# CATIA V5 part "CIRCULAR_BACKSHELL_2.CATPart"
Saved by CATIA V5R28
Part number: CIRCULAR_BACKSHELL_2
Revision: --A
Publications: "Logical Termination.1", "BCP", "BCPRPoint_generated(BCP)", "BCPPlane_generated(BCP)", "BaCP", "Face_generated(BaCP)", "Face_generated(BaCP).1", "MasterKeywayAxis", "Axis_generated(BaCP)"
Bounding box of the stored display mesh (mm): x 0 to 66.178, y -14.383 to 14.383, z -15.367 to 15.317
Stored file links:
  C:\Users\ajc8720\Documents\BOEING_WORK\0001-2CES\004-AP242\Boeing-Generic_Harness_R3\CIRCULAR_BACKSHELL_2.CATPart
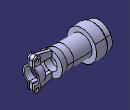
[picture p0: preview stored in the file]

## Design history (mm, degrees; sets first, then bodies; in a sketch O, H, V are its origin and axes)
Parameters
  PartNumber = "CIRCULAR_BACKSHELL_2"
AxisSystem1 "MasterKeywayAxis": origin (0, 0, 0), X (1, 0, 0), Y (0, 1, 0), Z (0, 0, 1)
Set1
  Point1: (34.417 {= Sketch2.distance(P3 V)}, 12.7, 0)
  Plane1: type 1Line1Pt, RefPoint Point1, Line Sketch2.L1
  Point2: type OnCurve, Support Sketch2.L4, Ratio 0.5
  Line1: type PtDir, RefPoint Point2, Direction (0, 1, 0), Start 0, End 5.08
  Point3: type OnCurve, Support Line1, Ratio 0.5
  Plane2: type 1Line1Pt, RefPoint Point3, Line Sketch2.L4
  Point4: type Center, Curve edge [face of Shaft1 from Sketch1.L5 | face of Shaft1 from Sketch1.L6]
  Plane3: type Tangent, Support face of Shaft1 from Sketch1.L5, RefPoint Point4
  Plane4: type OffsetPt, RefPlane Plane2, RefPoint Sketch2.P10
  Line2: type PtPt, FirstPoint vertex [face of Pad3 from Sketch5.L6 | face of Pad3 from Sketch5.L12 | end face of Pad3], SecondPoint vertex [face of Pad3 from Sketch5.L3 | face of Pad3 from Sketch5.L4 | start face of Pad3]
  Point5: type OnCurve, Support Line2, Ratio 0.5
  Plane5: type Tangent, Support face of Pad3 from Sketch5.L6, RefPoint Point5
Set2 "EGF"
  Set3 "BCP"
    Point6 "BCPRPoint": type Center, Curve edge [start face of Pad4 | face of Pad4 from Sketch6.A3]
    Plane6 "BCPPlane": type Tangent, Support start face of Pad4, RefPoint Point6
  Set4 "BaCP"
    Point7 "BaCPRPoint": type Center, Curve edge [face of Shaft1 from Sketch1.L6 | face of Shaft1 from Sketch1.L7]
    Plane7 "BaCPCPlane": type Tangent, Support face of Shaft1 from Sketch1.L7, RefPoint Point7
    Line3 "BaCPCLine": type PtDir, RefPoint Point7, Direction (0, 1, 0), Start 0, End 5.08
Body1 (main body)
  Sketch1 on xy-plane, origin (0, 0, 0), H (1, 0, 0), V (0, 1, 0)
    line L1 (0, 10.3124) -> (0, 12.7889)
    line L2 (0, 12.7889) -> (4.7625, 12.7889)
    point P3 (4.7625, 12.7889)
    line L3 (4.7625, 12.7889) -> (6.3754, 14.4018)
    line L4 (6.3754, 14.4018) -> (16.764, 14.4018)
    line L5 (16.764, 14.4018) -> (16.764, 6.477)
    line L6 (16.764, 6.477) -> (7.747, 6.477)
    line L7 (7.747, 6.477) -> (7.747, 10.3124)
    line L8 (7.747, 10.3124) -> (0, 10.3124)
    axis line L9 (-2.2417, 0) -> (20.7737, 0)
    point P9 (-2.2417, 0)
    distance P3 L1 = 4.7625
    angle L3 L4 = 45
    distance L1 L7 = 7.747
    distance L1 L5 = 16.764
    distance L6 H = 6.477
    distance L8 H = 10.3124
    distance L2 H = 12.7889
    distance L4 H = 14.4018
    vertical: L1 V, L5 V, L7 V
    horizontal: L2 H, L4 H, L6 H, L8 H, L9 H
    coincidence: L1 V, P9 H
  Shaft1: profile Sketch1, axis Sketch1.L9, angle 360
  Sketch2 on zx-plane, origin (0, 0, 0), H (-1, 0, 0), V (0, 0, 1)
    line L1 (-34.417, 0) -> (-34.4237, 15.3041)
    line L2 (-34.417, 0) -> (-36.5055, 0)
    point P3 (-34.417, 0)
    line L3 (-34.417, 0) -> (-40.767, -0.0055)
    line L4 (-40.767, -0.0055) -> (-40.6855, -93.3721)
    reference projected point E1 (-34.417, 0) from Point1
    point P7 (-40.767, -0.0055)
    line L5 (-47.117, -0.0111) -> (-47.0355, -93.3776)
    construction line L6 (-40.767, -0.0055) -> (-47.117, -0.0111)
    construction line L7 (-40.6855, -93.3721) -> (-47.0355, -93.3776)
    point P10 (-47.117, -0.0111)
    point P11 (-34.417, 0)
    angle L1 V = 0.025
    distance P3 V = 34.417
    distance L4 E1 = 6.35
    angle L3 H = 0.05
    distance L4 L5 = 6.35
    horizontal: L2 H
    coincidence: L2 P3, L1 P3, L2 H, L4 P7, L3 P7, L3 P10, L5 P10, L1 P11, L3 P11
    perpendicularity: L4 L3, L6 L4, L6 L5, L7 L4, L7 L5
  Sketch3 on Plane3, origin (16.764, 0, 0), H (0, -1, 0), V (0, 0, 1)
    circle A1 centre (0, 0) radius 6.477
    circle A2 centre (0, 0) radius 9.906
    radius A1 = 6.477
    radius A2 = 9.906
  Pad1: profile Sketch3, direction (1, 0, 0), up to Plane1
  Sketch4 on Plane2, origin (40.6592, 0, -123.5794), H (0, 1, 0), V (0.0009, 0, 1)
    circle A1 centre (0, 123.5739) radius 6.477
    point P1 (0, 123.5739)
    circle A2 centre (0, 123.5739) radius 9.906
    reference projected point E1 (0, 123.5739) from Sketch2.P7
    radius A1 = 6.477
    radius A2 = 9.906
    coincidence: P1 V, P1 E1
  Pad2: profile Sketch4, direction (-1, 0, 0.0009), up to Plane1
  Sketch5 on zx-plane, origin (0, 0, 0), H (-1, 0, 0), V (0, 0, 1)
    point P1 (0, 0)
    construction line L1 (0, 0) -> (-34.417, 0)
    point P2 (-34.417, 0)
    construction line L2 (-34.417, 0) -> (-47.117, -0.0111)
    point P3 (-47.117, -0.0111)
    point P4 (-47.0636, -61.233)
    line L3 (-66.1776, 12.1389) -> (-66.1725, 6.3223)
    point P5 (-66.1725, 6.3223)
    line L4 (-66.1725, 6.3223) -> (-59.8225, 6.3278)
    line L5 (-47.1226, 6.4659) -> (-47.127, 11.4756)
    circle A1 centre (-63.0026, 12.1417) radius 1.8256
    arc A2 centre (-63.0026, 12.1417) radius 3.175 from (-66.1776, 12.1389) to (-62.2384, 15.2233) cw
    point P7 (-66.1776, 12.1389)
    point P8 (-62.2383, 15.2233)
    point P10 (-66.1614, -6.3777)
    point P12 (-66.1564, -12.1943)
    line L6 (-66.1564, -12.1943) -> (-66.1614, -6.3777)
    circle A3 centre (-62.9814, -12.1915) radius 1.8256
    line L7 (-62.2384, 15.2233) -> (-47.127, 11.4756)
    point P13 (-62.2384, 15.2233)
    point P14 (-47.127, 11.4756)
    point P15 (-62.2118, -15.2718)
    point P16 (-66.1564, -12.1943)
    arc A4 centre (-62.9814, -12.1915) radius 3.175 from (-66.1564, -12.1943) to (-62.2118, -15.2718) ccw
    point P18 (-47.107, -11.4978)
    point P19 (-62.2118, -15.2718)
    line L8 (-62.2118, -15.2718) -> (-47.107, -11.4978)
    construction line L9 (-40.7756, 9.9005) -> (-97.5554, 23.9821)
    point P20 (-40.7756, 9.9005)
    line L10 (-59.8225, 6.3278) -> (-59.8226, 6.4548)
    line L11 (-59.8226, 6.4548) -> (-47.1226, 6.4659)
    point P22 (-59.8225, 6.3278)
    point P23 (-47.1226, 6.4659)
    point P24 (-59.8226, 6.4548)
    point P25 (-59.8114, -6.3722)
    point P26 (-66.1614, -6.3777)
    line L12 (-66.1614, -6.3777) -> (-59.8114, -6.3722)
    point P27 (-59.8113, -6.4992)
    point P28 (-59.8114, -6.3722)
    line L13 (-59.8114, -6.3722) -> (-59.8113, -6.4992)
    point P29 (-47.1113, -6.4881)
    point P30 (-59.8113, -6.4992)
    line L14 (-59.8113, -6.4992) -> (-47.1113, -6.4881)
    point P31 (-47.107, -11.4978)
    point P32 (-47.1113, -6.4881)
    line L15 (-47.1113, -6.4881) -> (-47.107, -11.4978)
    distance P1 P2 = 34.417
    angle L1 L2 = 0.05
    distance P3 P2 = 12.7
    distance L5 L3 = 19.05
    radius A1 = 1.8256
    radius A2 = 3.175
    distance L4 L2 = 6.35
    distance A2 L2 = 15.3416
    distance P20 L2 = 9.906
    distance P20 L5 = 6.35
    distance L10 L3 = 6.35
    distance L11 L2 = 6.477
    horizontal: L1 H
    coincidence: P1 O, L5 P3, L7 P8, P8 A2, P4 L5, L7 L9
    tangency: A2 L3, A2 L7, L9 A2
    concentricity: A1 A2
    symmetry: P5 P10 L2, P7 P12 L2, L3 L6 L2, A1 A3 L2, P13 P15 L2, P7 P16 L2, A2 A4 L2, P14 P18 L2, P13 P19 L2, L7 L8 L2, P22 P25 L2, P5 P26 L2, L4 L12 L2, P24 P27 L2, P22 P28 L2, L10 L13 L2, P23 P29 L2, P24 P30 L2, L11 L14 L2, P14 P31 L2, P23 P32 L2, L5 L15 L2
    parallelism: L4 L2, L3 L5, L11 L4
    perpendicularity: L3 L2
  Pad3: profile Sketch5, direction (0, 1, 0), length 1.5875, opposite side length 1.5875
  Sketch6 on Plane5, origin (65.9652, 0, -231.2478), H (0, -1, 0), V (0.0009, 0, 1)
    arc A1 centre (0, 231.2202) radius 6.5676 from (1.6764, 237.5702) to (1.6764, 224.8702) cw
    point P1 (0, 231.2202)
    point P2 (1.6764, 237.5702)
    line L1 (1.6764, 237.5702) -> (1.6764, 246.5618)
    point P3 (1.6764, 246.5618)
    line L2 (1.6764, 215.8786) -> (1.6764, 224.8702)
    point P4 (1.6764, 215.8786)
    point P5 (1.6764, 224.8702)
    line L3 (3.2639, 215.8786) -> (3.2639, 223.7468)
    point P6 (3.2639, 215.8786)
    point P7 (3.2639, 223.7468)
    arc A2 centre (0, 231.2202) radius 8.1551 from (3.2639, 223.7468) to (3.2639, 238.6936) ccw
    point P8 (3.2639, 238.6936)
    line L4 (3.2639, 238.6936) -> (3.2639, 246.5618)
    point P9 (3.2639, 246.5618)
    line L5 (1.6764, 215.8786) -> (3.2639, 215.8786)
    line L6 (1.6764, 246.5618) -> (3.2639, 246.5618)
    construction line L7 (0, 231.2202) -> (0, 27.9514)
    point P11 (-1.6764, 237.5702)
    point P12 (-1.6764, 246.5618)
    point P13 (-1.6764, 215.8786)
    point P14 (-1.6764, 224.8702)
    point P15 (-3.2639, 215.8786)
    point P16 (-3.2639, 223.7468)
    point P17 (-3.2639, 238.6936)
    point P18 (-3.2639, 246.5618)
    point P19 (0, 231.2202)
    arc A3 centre (0, 231.2202) radius 6.5676 from (-1.6764, 237.5702) to (-1.6764, 224.8702) ccw
    line L8 (-1.6764, 237.5702) -> (-1.6764, 246.5618)
    line L9 (-1.6764, 215.8786) -> (-1.6764, 224.8702)
    line L10 (-3.2639, 215.8786) -> (-3.2639, 223.7468)
    arc A4 centre (0, 231.2202) radius 8.1551 from (-3.2639, 223.7468) to (-3.2639, 238.6936) cw
    line L11 (-3.2639, 238.6936) -> (-3.2639, 246.5618)
    line L12 (-1.6764, 215.8786) -> (-3.2639, 215.8786)
    line L13 (-1.6764, 246.5618) -> (-3.2639, 246.5618)
    reference projected point E1 (0, 231.2202) from Point5
    distance L2 L3 = 1.5875
    distance L2 P1 = 1.6764
    distance A1 A2 H = 1.5875
    distance L5 P1 = 15.3416
    distance L6 P1 = 15.3416
    distance P5 P19 V = 6.35
    vertical: L1 V, L2 V, L7 V
    coincidence: P4 L1, L2 L1, L3 L4, P19 E1
    concentricity: A2 A1
    horizontal: L5 H, L6 H
    symmetry: P2 P11 L7, P3 P12 L7, P4 P13 L7, P5 P14 L7, P6 P15 L7, P7 P16 L7, P8 P17 L7, P9 P18 L7, A1 A3 L7, L1 L8 L7, L2 L9 L7, L3 L10 L7, A2 A4 L7, L4 L11 L7, L5 L12 L7, L6 L13 L7
  Pad4: profile Sketch6, direction (-1, 0, 0.0009), length 6.35
  Fillet1: radius 3.175 {= deleted_StrainReleaseWidth /2}, on edge [start face of Pad4 | face of Pad4 from Sketch6.L13]; edge [face of Pad4 from Sketch6.L13 | end face of Pad4]; edge [start face of Pad4 | face of Pad4 from Sketch6.L6]; edge [face of Pad4 from Sketch6.L6 | end face of Pad4]; edge [start face of Pad4 | face of Pad4 from Sketch6.L12]; edge [start face of Pad4 | face of Pad4 from Sketch6.L5]; edge [face of Pad4 from Sketch6.L12 | end face of Pad4]; edge [face of Pad4 from Sketch6.L5 | end face of Pad4]
  Sketch7 on face of Pad4 from Sketch6.L11, origin (72.7908, 3.2639, -31.7287), H (1, 0, 0), V (0, 0, -1)
    point P1 (-9.7882, -43.8704)
    reference projected arc E1 centre (-9.7882, -43.8704) radius 3.175 from (-7.5431, -46.1155) to (-7.5431, -41.6253) ccw from edge [face of Pad4 from Sketch6.L11 | face of Fillet1]
    concentricity: P1 E1
  Hole1: placed by Sketch7, at (63.0026, 3.2639, 12.1417) direction (0, -1, 0), diameter 3.175, up to face of Pad4 from Sketch6.L4
  Sketch8 on face of Pad4 from Sketch6.L10, origin (57.6407, 3.2639, -47.0401), H (1, 0, 0), V (0, 0, -1)
    point P1 (5.3407, -34.8486)
    reference projected arc E1 centre (5.3407, -34.8486) radius 3.175 from (7.5858, -32.6035) to (3.0956, -32.6035) ccw from edge [face of Pad4 from Sketch6.L10 | face of Fillet1]
    concentricity: P1 E1
  Hole2: placed by Sketch8, at (62.9814, 3.2639, -12.1915) direction (0, -1, 0), diameter 3.175, up to face of Pad4 from Sketch6.L3
  Sketch9 on zx-plane, origin (0, 0, 0), H (-1, 0, 0), V (0, 0, 1)
    construction line L1 (-24.3125, 0) -> (-34.417, 0)
    point P1 (-24.3125, 0)
    point P2 (-34.417, 0)
    construction line L2 (-34.417, 0) -> (-40.767, -0.0055)
    point P3 (-40.767, -0.0055)
    construction line L3 (-40.767, -0.0055) -> (-40.7288, -43.7991)
    line L4 (-47.127, 11.4756) -> (-40.7756, 9.9005)
    point P6 (-40.7756, 9.9005)
    line L5 (-40.7756, 9.9005) -> (-40.7726, 6.4715)
    line L6 (-40.7726, 6.4715) -> (-47.1226, 6.4659)
    line L7 (-47.1226, 6.4659) -> (-47.127, 11.4756)
    axis line L8 (-40.767, -0.0055) -> (-90.9431, -0.0493)
    reference projected point E1 (-47.127, 11.4756) from edge [face of Pad3 from Sketch5.L7 | face of Pad3 from Sketch5.L5]
    distance P2 V = 34.417
    angle L1 L2 = 0.05
    distance P2 P3 = 6.35
    distance P6 L2 = 9.906 {= Sketch3.radius(A2)}
    distance L5 L7 = 6.35
    distance L6 L2 = 6.477
    coincidence: P1 H, L5 L3, L4 E1
    horizontal: L1 H
    perpendicularity: L3 L2
    parallelism: L8 L2
  Shaft2: profile Sketch9, axis Sketch9.L8, angle 360
Body2 "BaCP"
  Sketch10 "Sketch" on Plane7, origin (7.747, 0, 0), H (0, 1, 0), V (0, 0, 1)
    line L1 (-0.672, 0.762) -> (0.672, 0.762)
    point P1 (-0.672, 0.762)
    point P2 (0.672, 0.762)
    arc A1 centre (0, 0) radius 1.016 from (-1.016, 0) to (1.016, 0) ccw
    point P3 (0, 0)
    point P4 (-1.016, 0)
    point P5 (1.016, 0)
    reference projected point E1 (0, 0) from Point7
    arc A2 centre (0, 0) radius 1.016 from (1.016, 0) to (0.672, 0.762) ccw
    point P6 (0, 0)
    point P7 (1.016, 0)
    point P8 (0.672, 0.762)
    arc A3 centre (0, 0) radius 1.016 from (-0.672, 0.762) to (-1.016, 0) ccw
    point P9 (0, 0)
    point P10 (-0.672, 0.762)
    point P11 (-1.016, 0)
    reference projected point E2 (0, 0) from Point7
    reference projected point E3 (0, 0) from Point7
    length L1 = 1.344
    radius A1 = 1.016
    radius A3 = 1.016
    radius A2 = 1.016
    distance L1 P5 = 0.762
    distance P4 L1 = 0.762
    distance P7 L1 = 0.762
    distance P11 L1 = 0.762
    coincidence: P3 E1, P6 E2, P9 E3, P8 P2, P10 P1
    horizontal: L1 H
  Pad5: profile Sketch10, direction (1, 0, 0), length 0.508, opposite side up to Plane7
